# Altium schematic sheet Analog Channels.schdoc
size 297 x 209 mm; Symbol: Drawing-Symbol_A4; @Project Name: Pedal Steel; @Page Count: 1; @Update Date: 2026-10-20; @Create Date: 2026-10-20; @Schematic Name: Schematic1; @Page No: 1; @Page Name: P1; Company: EasyEDA.com; Version: V1.0; Page Size: A4; Device: Drawing-Symbol_A4; @Create Time: 16:28:57; @Update Time: 16:28:57; Border: 1; Width: 1170; Height: 825; Region Start: 1; X Region Count: 6; Y Region Count: 4; Blade Width: 10; Title Block Position: 3
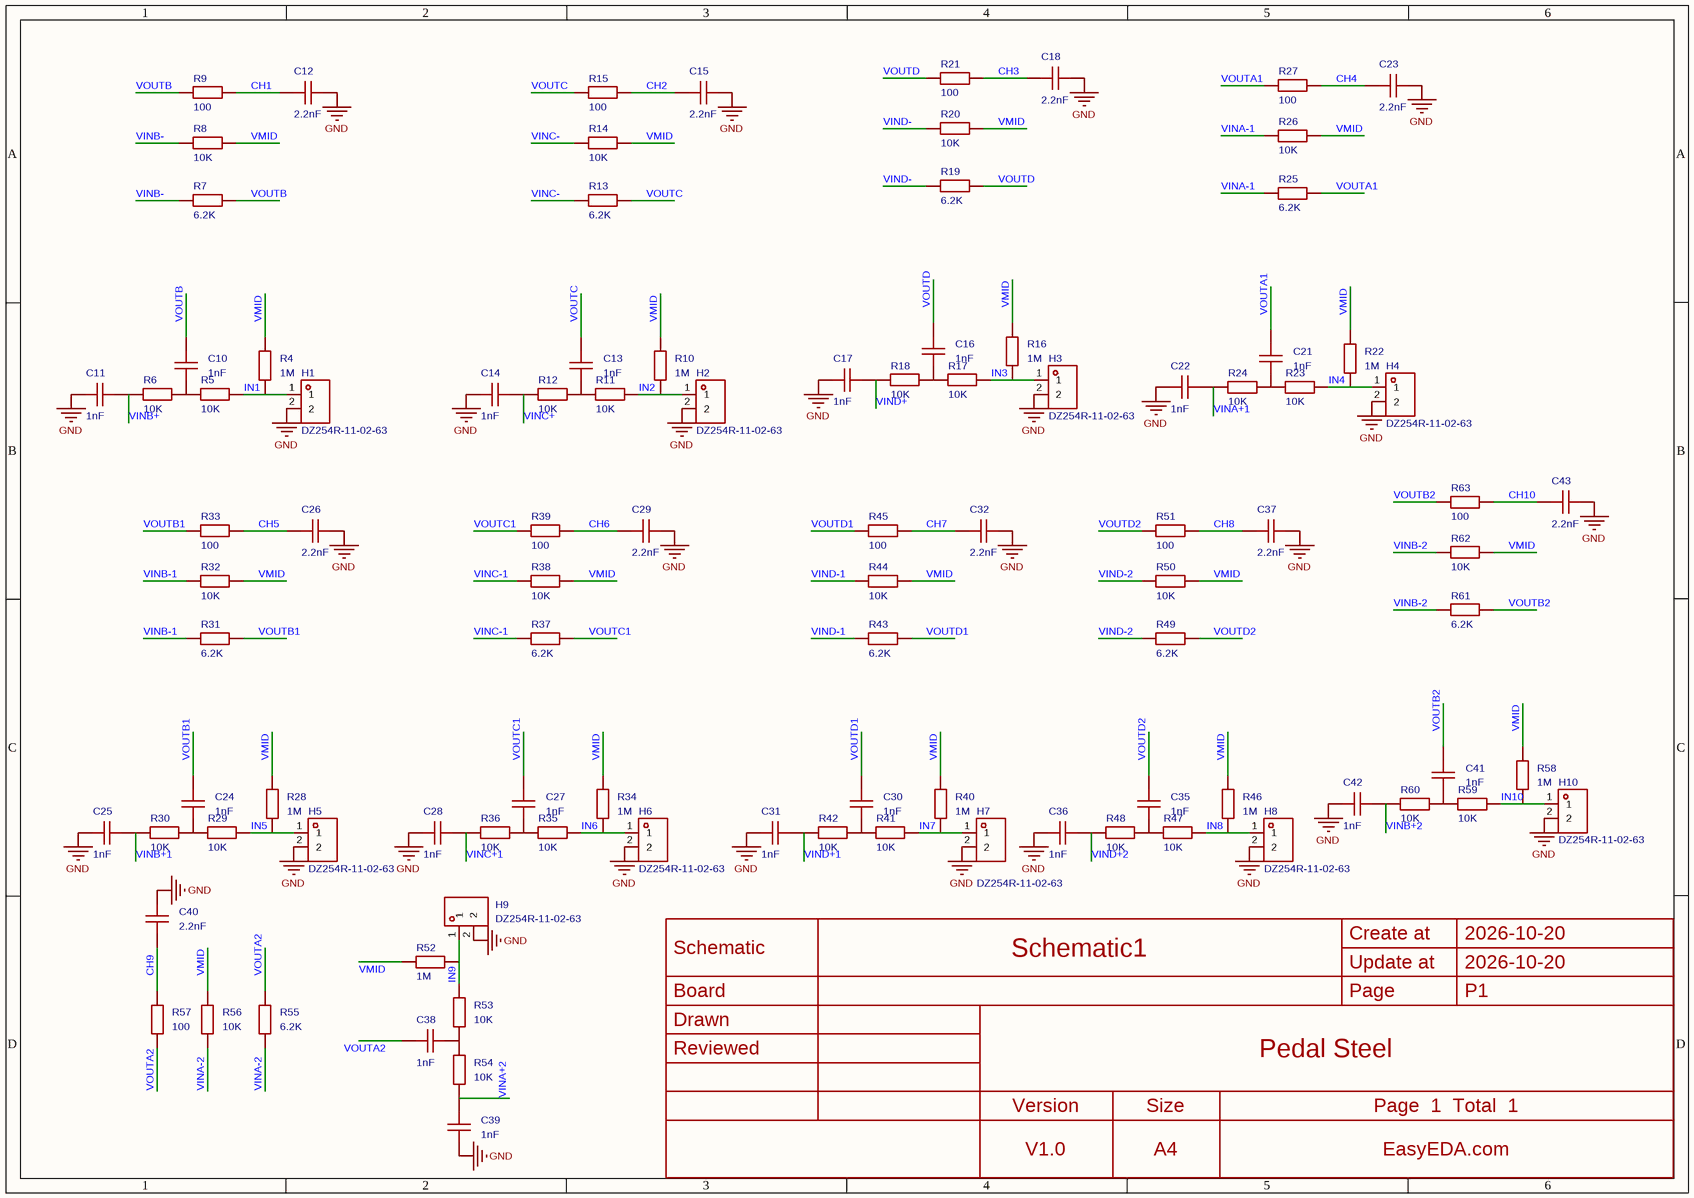
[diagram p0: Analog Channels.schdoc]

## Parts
C10  1nF  [C0603]
C11  1nF  [C0603]
C12  2.2nF  [C0603]
C13  1nF  [C0603]
C14  1nF  [C0603]
C15  2.2nF  [C0603]
C16  1nF  [C0603]
C17  1nF  [C0603]
C18  2.2nF  [C0603]
C21  1nF  [C0603]
C22  1nF  [C0603]
C23  2.2nF  [C0603]
C24  1nF  [C0603]
C25  1nF  [C0603]
C26  2.2nF  [C0603]
C27  1nF  [C0603]
C28  1nF  [C0603]
C29  2.2nF  [C0603]
C30  1nF  [C0603]
C31  1nF  [C0603]
C32  2.2nF  [C0603]
C35  1nF  [C0603]
C36  1nF  [C0603]
C37  2.2nF  [C0603]
C38  1nF  [C0603]
C39  1nF  [C0603]
C40  2.2nF  [C0603]
C41  1nF  [C0603]
C42  1nF  [C0603]
C43  2.2nF  [C0603]
H1  DZ254R-11-02-63  [HDR-TH_2P-P2.54-V-M-1]
H2  DZ254R-11-02-63  [HDR-TH_2P-P2.54-V-M-1]
H3  DZ254R-11-02-63  [HDR-TH_2P-P2.54-V-M-1]
H4  DZ254R-11-02-63  [HDR-TH_2P-P2.54-V-M-1]
H5  DZ254R-11-02-63  [HDR-TH_2P-P2.54-V-M-1]
H6  DZ254R-11-02-63  [HDR-TH_2P-P2.54-V-M-1]
H7  DZ254R-11-02-63  [HDR-TH_2P-P2.54-V-M-1]
H8  DZ254R-11-02-63  [HDR-TH_2P-P2.54-V-M-1]
H9  DZ254R-11-02-63  [HDR-TH_2P-P2.54-V-M-1]
H10  DZ254R-11-02-63  [HDR-TH_2P-P2.54-V-M-1]
R4  1M  [R0603]
R5  10K  [R0603]
R6  10K  [R0603]
R7  6.2K  [R0603]
R8  10K  [R0603]
R9  100  [R0603]
R10  1M  [R0603]
R11  10K  [R0603]
R12  10K  [R0603]
R13  6.2K  [R0603]
R14  10K  [R0603]
R15  100  [R0603]
R16  1M  [R0603]
R17  10K  [R0603]
R18  10K  [R0603]
R19  6.2K  [R0603]
R20  10K  [R0603]
R21  100  [R0603]
R22  1M  [R0603]
R23  10K  [R0603]
R24  10K  [R0603]
R25  6.2K  [R0603]
R26  10K  [R0603]
R27  100  [R0603]
R28  1M  [R0603]
R29  10K  [R0603]
R30  10K  [R0603]
R31  6.2K  [R0603]
R32  10K  [R0603]
R33  100  [R0603]
R34  1M  [R0603]
R35  10K  [R0603]
R36  10K  [R0603]
R37  6.2K  [R0603]
R38  10K  [R0603]
R39  100  [R0603]
R40  1M  [R0603]
R41  10K  [R0603]
R42  10K  [R0603]
R43  6.2K  [R0603]
R44  10K  [R0603]
R45  100  [R0603]
R46  1M  [R0603]
R47  10K  [R0603]
R48  10K  [R0603]
R49  6.2K  [R0603]
R50  10K  [R0603]
R51  100  [R0603]
R52  1M  [R0603]
R53  10K  [R0603]
R54  10K  [R0603]
R55  6.2K  [R0603]
R56  10K  [R0603]
R57  100  [R0603]
R58  1M  [R0603]
R59  10K  [R0603]
R60  10K  [R0603]
R61  6.2K  [R0603]
R62  10K  [R0603]
R63  100  [R0603]

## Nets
GND: C11.2 C12.1 C14.2 C15.1 C17.2 C18.1 C22.2 C23.1 C25.2 C26.1 C28.2 C29.1 C31.2 C32.1 C36.2 C37.1 C39.2 C40.1 C42.2 C43.1 H1.2 H2.2 H3.2 H4.2 H5.2 H6.2 H7.2 H8.2 H9.2 H10.2
CH1: C12.2 R9.2
CH2: C15.2 R15.2
CH3: C18.2 R21.2
CH4: C23.2 R27.2
CH5: C26.2 R33.2
CH6: C29.2 R39.2
CH7: C32.2 R45.2
CH8: C37.2 R51.2
CH9: C40.2 R57.2
CH10: C43.2 R63.2
IN1: H1.1 R4.1 R5.2
IN2: H2.1 R10.1 R11.2
IN3: H3.1 R16.1 R17.2
IN4: H4.1 R22.1 R23.2
IN5: H5.1 R28.1 R29.2
IN6: H6.1 R34.1 R35.2
IN7: H7.1 R40.1 R41.2
IN8: H8.1 R46.1 R47.2
IN9: H9.1 R52.1 R53.2
IN10: H10.1 R58.1 R59.2
VINA+1: C22.1 R24.1
VINA+2: C39.1 R54.1
VINA-1: R25.1 R26.1
VINA-2: R55.1 R56.1
VINB+: C11.1 R6.1
VINB+1: C25.1 R30.1
VINB+2: C42.1 R60.1
VINB-: R7.1 R8.1
VINB-1: R31.1 R32.1
VINB-2: R61.1 R62.1
VINC+: C14.1 R12.1
VINC+1: C28.1 R36.1
VINC-: R13.1 R14.1
VINC-1: R37.1 R38.1
VIND+: C17.1 R18.1
VIND+1: C31.1 R42.1
VIND+2: C36.1 R48.1
VIND-: R19.1 R20.1
VIND-1: R43.1 R44.1
VIND-2: R49.1 R50.1
VMID: R4.2 R8.2 R10.2 R14.2 R16.2 R20.2 R22.2 R26.2 R28.2 R32.2 R34.2 R38.2 R40.2 R44.2 R46.2 R50.2 R52.2 R56.2 R58.2 R62.2
VOUTA1: C21.1 R25.2 R27.1
VOUTA2: C38.1 R55.2 R57.1
VOUTB: C10.1 R7.2 R9.1
VOUTB1: C24.1 R31.2 R33.1
VOUTB2: C41.1 R61.2 R63.1
VOUTC: C13.1 R13.2 R15.1
VOUTC1: C27.1 R37.2 R39.1
VOUTD: C16.1 R19.2 R21.1
VOUTD1: C30.1 R43.2 R45.1
VOUTD2: C35.1 R49.2 R51.1
NetC10_2: C10.2 R5.1 R6.2
NetC13_2: C13.2 R11.1 R12.2
NetC16_2: C16.2 R17.1 R18.2
NetC21_2: C21.2 R23.1 R24.2
NetC24_2: C24.2 R29.1 R30.2
NetC27_2: C27.2 R35.1 R36.2
NetC30_2: C30.2 R41.1 R42.2
NetC35_2: C35.2 R47.1 R48.2
NetC38_2: C38.2 R53.1 R54.2
NetC41_2: C41.2 R59.1 R60.2

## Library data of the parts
C10-C18 C21-C32 C35-C43 = CAP_0603: Symbol: CAP_OLD; ConvertToPcb: yes; ModelId: 624118aa3cc7497086c383c2d72e08520819f05c4eef4c71ace90d822a990e87; ModelName: C0603_L1.6-W0.8-H0.8; ModelTransform: 62.992,31.496,0,0,0,0,0,0,0
H1-H10 = DZ254R-11-02-63: Pin Structure:1x2P Pitch:2.54mm Row Spacing:- Circluar Pins/Square Pins:Pin Header Mounting Type:Through Hole Number of Rows:1 Number of Pins:2P Current Rating:3A Voltage Rating (Max):- Length of Mating Pin:6mm Insulation Height:2.54mm Length of End Conne; Manufacturer: DEALON(德艺隆); AddInBom: yes; ModelId: e506c2b6a89c4aacb020357246aab7250819f05c4eef4c71ace90d822a990e87; ModelName: HDR-M-2.54_1x2; ModelTransform: 200,100,0,0,0,0,0,0,-118.11; Pin Structure: 1x2P; Pitch: 2.54mm; Current Rating: 3A
R4-R63 = Res_0603: Symbol: Res; ConvertToPcb: yes; ModelId: 112863783b5b41f1b5254f87eedc79320819f05c4eef4c71ace90d822a990e87; ModelTransform: 31.8897,63.7794,0,90,0,0,0,0,0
